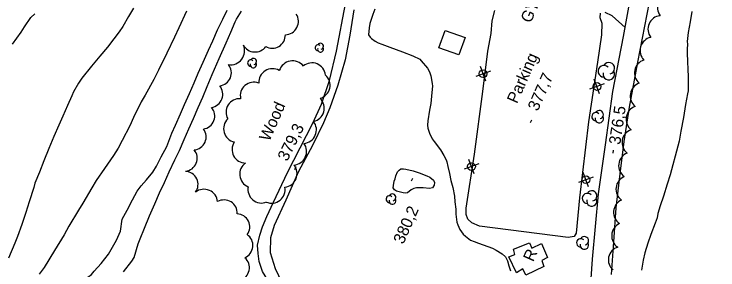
# Model space of a CAD drawing. Extents: x 287698 to 290158, y 5234163 to 5237182.
# Drawn here: x 288774.6 to 288956.3, y 5234855.5 to 5234921.6 of the extents above; entities that cross this region are included whole.
import ezdxf

# ---------------------------------------------------------------- set-up
doc = ezdxf.new("R2010")
doc.units = 0
for name, color, linetype in [('Niveau 1', 7, 'Continuous'), ('Niveau 19', 7, 'Continuous'), ('Niveau 2', 7, 'Continuous'), ('Niveau 21', 7, 'Continuous'), ('Niveau 3', 7, 'Continuous'), ('Niveau 31', 7, 'Continuous'), ('Niveau 36', 7, 'Continuous'), ('Niveau 44', 7, 'Continuous'), ('Niveau 52', 7, 'Continuous')]:
    doc.layers.add(name, color=color, linetype=linetype)

msp = doc.modelspace()

# ---------------------------------------------------------------- linework, layer by layer
at = {"layer": 'Niveau 1'}
for points in [[(288774.17, 5234913.81), (288776.43, 5234916.88), (288777.24, 5234918.29), (288778.95, 5234920.67), (288779.93, 5234921.69)], [(288880.18, 5234876.71), (288878.46, 5234876.71), (288877.8, 5234876.57), (288877.12, 5234876.24), (288876.16, 5234875.43), (288875.57, 5234875.31), (288875.06, 5234875.4), (288873.31, 5234875.84), (288872.77, 5234876.22), (288872.47, 5234876.73), (288872.51, 5234877.3), (288872.71, 5234878.44), (288872.97, 5234879.08), (288873.1, 5234879.85), (288873.53, 5234880.81), (288873.97, 5234881.3), (288874.39, 5234881.62), (288875.08, 5234881.62), (288875.69, 5234881.51), (288877.63, 5234881.11), (288879.11, 5234880.62), (288881.14, 5234879.86), (288881.89, 5234879.46), (288882.87, 5234878.7), (288883.13, 5234878.08), (288883.06, 5234877.38), (288882.57, 5234876.76), (288881.86, 5234876.56), (288880.18, 5234876.71)]]:
    msp.add_lwpolyline(points, dxfattribs=at)
at = {"layer": 'Niveau 19'}
for points in [[(288839.86, 5234869.3), (288841.53, 5234872.99), (288845.2, 5234880.65), (288851.7, 5234893.44), (288853.92, 5234898.35), (288856.04, 5234904.47), (288857.79, 5234911.98), (288860.11, 5234924.2)], [(288862.3, 5234922.68), (288861.25, 5234916.18), (288860.09, 5234909.73), (288858.16, 5234903.22), (288856.12, 5234897.35), (288854.45, 5234893.48), (288851.58, 5234887.67), (288847.97, 5234880.93), (288844.71, 5234873.51), (288841.72, 5234867.03), (288840.74, 5234863.77), (288840.7, 5234859.98), (288841.98, 5234855.92), (288843.73, 5234852.3)], [(288857.44, 5234838.79), (288853.16, 5234839.45), (288850.82, 5234840.45), (288848.62, 5234841.61), (288846.58, 5234843.94), (288841.74, 5234850.38), (288840.13, 5234852.86), (288838.68, 5234855.1), (288837.81, 5234857.67), (288837.57, 5234859.79), (288837.44, 5234861.9), (288838.04, 5234864.52), (288838.71, 5234866.69), (288839.86, 5234869.3)]]:
    msp.add_lwpolyline(points, dxfattribs=at)
at = {"layer": 'Niveau 2'}
for points in [[(288805.44, 5234923.13), (288804.15, 5234921), (288802.66, 5234918.39), (288801.74, 5234916.97), (288800.32, 5234915.22), (288798.69, 5234913.04), (288796.71, 5234910.68), (288794.54, 5234908.12), (288792.11, 5234905.02), (288791.25, 5234903.79), (288789.96, 5234901.48), (288789.53, 5234900.5), (288788.39, 5234897.99), (288787.16, 5234895.2), (288786.15, 5234892.91), (288784.84, 5234889.95), (288783.54, 5234886.85), (288782.25, 5234883.71), (288781.11, 5234880.79), (288779.98, 5234877.93), (288779.65, 5234876.82), (288778.47, 5234873.13)], [(288819.07, 5234922.36), (288817.08, 5234918.06), (288815.98, 5234915.65), (288813.98, 5234911.48), (288811.91, 5234907.12), (288810.64, 5234904.67), (288808.44, 5234900.61), (288807.43, 5234898.89), (288805.43, 5234894.84), (288804.46, 5234892.72), (288802.53, 5234888.93), (288801.46, 5234886.98), (288800.25, 5234885.07), (288797.96, 5234881.68), (288795.79, 5234878.59), (288794.7, 5234876.75), (288792.35, 5234872.79), (288791.21, 5234870.97), (288788.75, 5234866.83), (288787.53, 5234864.62), (288785.02, 5234860.51), (288782.39, 5234856.18), (288781.1, 5234854.39)], [(288802.06, 5234865.55), (288802.53, 5234868.62), (288803.76, 5234870.96), (288805.16, 5234873.58), (288806.4, 5234875.89), (288807.38, 5234877.25), (288808.79, 5234878.82), (288810.37, 5234880.76), (288811.31, 5234882.33), (288812.59, 5234884.72), (288814.06, 5234887.4), (288814.3, 5234888.04), (288815.35, 5234890.85), (288816.24, 5234892.94), (288817.51, 5234895.83), (288818.58, 5234898.25), (288819.83, 5234901.08), (288821.05, 5234903.85), (288822.13, 5234906.32), (288823.41, 5234909.21), (288824.8, 5234912.3), (288825.87, 5234914.72), (288827.13, 5234917.5), (288828.48, 5234920.28), (288829.55, 5234922.64)], [(288832, 5234920.25), (288833.27, 5234922.32)], [(288867.71, 5234922.82), (288867.19, 5234921.49), (288866.41, 5234919.13), (288866.21, 5234918.02), (288866.09, 5234916.26), (288866.47, 5234915.66), (288866.88, 5234915.25), (288867.82, 5234914.59), (288868.6, 5234914.17), (288869.53, 5234913.78), (288871.59, 5234913.05), (288874.87, 5234911.83), (288877.53, 5234910.77), (288879.3, 5234909.91), (288879.66, 5234909.54), (288881.34, 5234907.62), (288881.86, 5234906.65), (288882.16, 5234905.61), (288882.53, 5234903.69), (288882.56, 5234902.94), (288882.46, 5234901.35), (288882.14, 5234898.48), (288881.84, 5234896.79), (288881.35, 5234894.01), (288881.3, 5234892.88), (288881.42, 5234892.17), (288881.85, 5234890.82), (288882.53, 5234889.38), (288883.04, 5234888.72), (288884.67, 5234886.54), (288885.55, 5234885.11), (288886.14, 5234883.97), (288886.28, 5234883.47), (288886.53, 5234882.25), (288887, 5234880.42), (288887.33, 5234878.62), (288887.8, 5234876.77), (288888.28, 5234874.57), (288888.38, 5234873.13), (288888.6, 5234871.2), (288888.62, 5234869.92), (288888.85, 5234867.85), (288889.09, 5234867.18), (288889.63, 5234865.99), (288890.54, 5234864.77), (288891.13, 5234864.22), (288892.41, 5234863.2), (288893.32, 5234862.82), (288894.43, 5234862.44), (288896.88, 5234861.6), (288898.05, 5234861.11), (288899.06, 5234860.59), (288900.59, 5234859.69), (288901.43, 5234858.93), (288901.97, 5234857.86), (288902.27, 5234856.57), (288902.7, 5234855.32)], [(288949.57, 5234922.25), (288949.1, 5234919.61), (288948.61, 5234916.81), (288948.33, 5234914.53), (288948.37, 5234913.83), (288948.29, 5234912.5), (288948.34, 5234911.36), (288948.45, 5234909.49), (288948.46, 5234907.11), (288948.55, 5234905.63), (288948.62, 5234903.31), (288948.56, 5234901.79), (288948.42, 5234900.99), (288947.93, 5234898.25), (288947.34, 5234894.86), (288946.73, 5234891.39), (288946.27, 5234888.79), (288945.95, 5234887.47), (288945.21, 5234884.86), (288944.64, 5234882.7), (288943.9, 5234880.07), (288943.14, 5234877.65), (288942.2, 5234874.59), (288941.35, 5234872.07), (288940.75, 5234870.09), (288940.55, 5234868.93), (288940.05, 5234867.57), (288938.99, 5234864.71), (288938.21, 5234862.45), (288937.44, 5234859.91), (288936.96, 5234858), (288936.5, 5234855.42)], [(288802.81, 5234855.03), (288804.97, 5234857.79), (288805.63, 5234858.77), (288806.63, 5234862.29), (288807.16, 5234863.59), (288808.29, 5234866.3), (288809.58, 5234869.5), (288810.9, 5234872.56), (288812.15, 5234875.4), (288813.38, 5234878.12), (288814.66, 5234880.82), (288816.07, 5234883.99), (288817.27, 5234886.36), (288818.5, 5234889.17), (288819.69, 5234891.95), (288820.89, 5234894.66), (288822.12, 5234897.44), (288823.31, 5234900.15), (288824.41, 5234902.86), (288825.71, 5234905.97), (288827.55, 5234910.14), (288829.32, 5234914.14), (288830.54, 5234916.93), (288831.7, 5234919.56), (288832, 5234920.25)], [(288778.47, 5234873.13), (288777.61, 5234870.33), (288776.59, 5234867.24), (288775.49, 5234864.18), (288774.78, 5234862.41), (288773.16, 5234858.6)], [(288797.03, 5234857.19), (288798.93, 5234859.57), (288801.03, 5234863.19), (288802.06, 5234865.55)], [(288774.12, 5234837.27), (288776.28, 5234839.62), (288777.32, 5234840.61), (288779.52, 5234842.9), (288781.21, 5234844.79), (288782.92, 5234846.9), (288784.86, 5234848.87), (288785.35, 5234849.15), (288787.78, 5234850.75), (288789.89, 5234851.89), (288791.11, 5234852.39), (288793.65, 5234853.66), (288794.56, 5234854.36), (288795.28, 5234855.21), (288797.03, 5234857.19)]]:
    msp.add_lwpolyline(points, dxfattribs=at)
at = {"layer": 'Niveau 21'}
for points in [[(288922.94, 5234844.51), (288923.87, 5234858.3), (288925.42, 5234875.13), (288927.29, 5234887.83), (288929.11, 5234901.59), (288931.93, 5234915.83), (288933.92, 5234927.24), (288936.33, 5234942.64), (288937.38, 5234949.4), (288938.45, 5234954.47), (288939.61, 5234958.71), (288941.21, 5234963.3), (288943.54, 5234967.66), (288946.48, 5234973.06), (288949.16, 5234979.57), (288952.18, 5234987.51), (288955.03, 5234994.58), (288959.1, 5235002.7)], [(288959.42, 5234990.64), (288955.67, 5234983.34), (288953.1, 5234975.97), (288949.25, 5234966.62), (288946.73, 5234960.36), (288945.04, 5234954), (288942.16, 5234941.12), (288939.76, 5234930.98), (288935.54, 5234909.21), (288933.35, 5234897.51), (288931.99, 5234888.65), (288930.97, 5234880.34), (288929.91, 5234871.55), (288929.29, 5234862.75), (288928.74, 5234854.31)]]:
    msp.add_lwpolyline(points, dxfattribs=at)
at = {"layer": 'Niveau 3'}
for p, q in [((288907.9, 5234893.56), (288908.22, 5234894.29)), ((288929.21, 5234885.66), (288929.35, 5234886.44)), ((288847.04, 5234881.48), (288847.4, 5234882.19)), ((288877.17, 5234878.49), (288877.49, 5234879.22))]:
    msp.add_line(p, q, dxfattribs=at)
at = {"layer": 'Niveau 31'}
for points in [[(288889.4, 5234911.03), (288884.25, 5234912.85), (288885.84, 5234917.36), (288890.99, 5234915.54)], [(288911.35, 5234856.38), (288906.65, 5234854.16), (288905.94, 5234855.77), (288904.24, 5234854.79), (288902.29, 5234858.91), (288903.82, 5234859.53), (288903.47, 5234860.86), (288907.65, 5234862.49), (288908.26, 5234861.13), (288910.75, 5234862.31), (288912.3, 5234858.69), (288910.79, 5234857.92)]]:
    msp.add_lwpolyline(points, close=True, dxfattribs=at)
at = {"layer": 'Niveau 36'}
for p, q in [((288897.54, 5234906.86), (288893.79, 5234905.49)), ((288896.35, 5234904.3), (288894.98, 5234908.05)), ((288926.91, 5234903.57), (288923.16, 5234902.2)), ((288925.72, 5234901.01), (288924.35, 5234904.76)), ((288893.34, 5234880.32), (288891.97, 5234884.07)), ((288894.53, 5234882.88), (288890.78, 5234881.51)), ((288922.88, 5234876.94), (288921.51, 5234880.69)), ((288924.07, 5234879.5), (288920.32, 5234878.13))]:
    msp.add_line(p, q, dxfattribs=at)
for centre in [(288895.66, 5234906.18), (288925.03, 5234902.89), (288892.65, 5234882.2), (288922.19, 5234878.82)]:
    msp.add_ellipse(centre, major_axis=(-0.907, 0.42), ratio=0.999982, dxfattribs=at)
at = {"layer": 'Niveau 44'}
for centre, radius, start, end in [((288853.05, 5234912.91), 0.754, 44.1154, 269.804), ((288853.7, 5234912.53), 0.754, 166.9369, 29.6212), ((288853.7, 5234913.29), 0.754, 282.2692, 149.7263), ((288835.67, 5234908.94), 0.811, 44.1154, 269.804), ((288836.36, 5234908.54), 0.811, 166.9369, 29.6212), ((288836.36, 5234909.35), 0.811, 282.2692, 149.7263), ((288846.47, 5234905.88), 3.61, 39.5583, 161.2791), ((288851.48, 5234905.47), 3.51, 6.2069, 129.3802), ((288928.11, 5234907.58), 1.49, 282.2692, 149.7263), ((288827.28, 5234906.43), 3.4, 276.626, 38.4458), ((288841.31, 5234903.91), 3.58, 60.901, 182.4101), ((288926.83, 5234906.83), 1.49, 44.1154, 269.804), ((288928.11, 5234906.08), 1.49, 166.9369, 29.6212), ((288825.07, 5234900.86), 3.4, 278.3012, 40.1357), ((288936.06, 5234894.42), 3.5, 109.1073, 230.9202), ((288822.98, 5234895.27), 3.4, 278.6015, 40.6921), ((288924.74, 5234895.1), 1.06, 44.1154, 269.804), ((288925.65, 5234895.63), 1.06, 282.2692, 149.7263), ((288832.18, 5234891.99), 3.51, 134.1647, 257.5986), ((288925.65, 5234894.57), 1.06, 166.9369, 29.6212), ((288820.78, 5234889.88), 3.39, 275.0891, 36.8088), ((288834.36, 5234886.64), 3.51, 146.5809, 269.8698), ((288934.13, 5234882.46), 3.49, 112.3632, 234.4801), ((288836.34, 5234880.24), 3.51, 124.4895, 247.7811), ((288823.59, 5234872.79), 3.56, 5.8222, 127.8048), ((288838.44, 5234876.3), 3.5, 168.6226, 292.4048), ((288923.71, 5234874.64), 1.33, 282.2692, 149.7263), ((288871.5, 5234873.8), 0.884, 44.1154, 269.804), ((288872.26, 5234874.25), 0.884, 282.2692, 149.7263), ((288922.56, 5234873.98), 1.33, 44.1154, 269.804), ((288872.26, 5234873.36), 0.884, 166.9369, 29.6212), ((288923.71, 5234873.31), 1.33, 166.9369, 29.6212), ((288920.86, 5234862.49), 1.09, 44.1154, 269.804), ((288921.8, 5234863.04), 1.09, 282.2692, 149.7263), ((288921.8, 5234861.94), 1.09, 166.9369, 29.6212), ((288831.92, 5234856.09), 3.41, 287.7706, 49.3451)]:
    msp.add_arc(centre, radius, start, end, dxfattribs=at)
for centre, major_axis, ratio, start_param, end_param in [((288944.18, 5234923.2), (2, -2.86), 0.999984, 2.594488, 4.7227), ((288844.54, 5234919.7), (3.05, -1.61), 0.999802, 5.21778, 7.349791), ((288941.69, 5234917.69), (2.11, -2.79), 0.999984, 2.594948, 4.718167), ((288841.2, 5234916.18), (2.97, 1.67), 0.999984, 3.692074, 5.788816), ((288939.65, 5234912.15), (-3.28, 1.21), 0.999022, 5.278382, 7.406117), ((288830.46, 5234912.13), (2.89, -2.21), 0.99998, 5.220334, 7.34848), ((288836.79, 5234915.2), (3.41, -0.01), 0.999984, 3.636306, 5.660231), ((288938.22, 5234906.4), (-3.43, 0.67), 0.999351, 5.220405, 7.344095), ((288852.65, 5234903.22), (0.8, 3.41), 0.999985, 3.635313, 5.789465), ((288836.49, 5234900.48), (-2.65, -2.3), 0.999985, 3.637338, 5.78744), ((288937.11, 5234900.44), (-3.27, 1.22), 0.999887, 5.404538, 7.533363), ((288832.81, 5234896.22), (-1.89, -2.96), 0.999985, 3.637316, 5.787462), ((288851.15, 5234897.27), (0.96, 3.37), 0.999985, 3.63454, 5.790238), ((288849.13, 5234891.69), (3.15, -1.54), 0.999916, 5.251281, 7.402421), ((288934.99, 5234888.4), (-3.43, 0.61), 0.999995, 5.219885, 7.349576), ((288846.58, 5234886.12), (3.19, -1.48), 0.999915, 5.216723, 7.346105), ((288818.47, 5234884.36), (1.27, 3.14), 0.999984, 3.638589, 5.786189), ((288844.12, 5234880.37), (2.99, -1.85), 0.999772, 5.376843, 7.529209), ((288818.69, 5234877.6), (-1.45, 3.05), 0.999984, 3.634173, 5.790605), ((288933.43, 5234876.39), (-3.47, 0.42), 0.999462, 5.222786, 7.344502), ((288841.07, 5234876.26), (2.74, 2.17), 0.999985, 3.632134, 5.792644), ((288828.81, 5234870.22), (-2.87, 1.78), 0.999984, 3.636175, 5.788602), ((288932.82, 5234870.39), (-3.42, 0.72), 0.999769, 5.34981, 7.472852), ((288832.04, 5234866.63), (-1.47, 3.04), 0.999984, 3.633366, 5.791411), ((288932.33, 5234864.31), (1.52, -3.14), 0.999995, 3.119261, 5.242697), ((288832.79, 5234861.84), (3.42, -0.36), 0.999994, 5.220078, 7.346066), ((288931.49, 5234858.12), (-3.43, 0.69), 0.98774, 5.226471, 7.332003)]:
    msp.add_ellipse(centre, major_axis=major_axis, ratio=ratio, start_param=start_param, end_param=end_param, dxfattribs=at)
at = {"layer": 'Niveau 52'}
for points in [[(288925.9, 5234921.83), (288925.75, 5234920.74), (288926.33, 5234919.2), (288926.23, 5234916.21), (288925.21, 5234909.14), (288922.85, 5234893.8), (288920.5, 5234874.15), (288919.7, 5234865.03), (288919.14, 5234864.15), (288917.65, 5234863.86), (288894.76, 5234866.84), (288892.72, 5234867.71), (288891.73, 5234868.66), (288891.24, 5234869.82), (288891.25, 5234871.48), (288893.46, 5234885.39), (288895.57, 5234901.61), (288896.89, 5234912), (288897.76, 5234916.6), (288898.01, 5234919.86), (288898.66, 5234922.49)], [(288932.33, 5234918.1), (288928.99, 5234921.15), (288927.19, 5234921.99)]]:
    msp.add_lwpolyline(points, dxfattribs=at)

# ---------------------------------------------------------------- texts
at = {"layer": 'Niveau 3'}
for s, rotation, p in [('377,7', 66.1217, (288909.76, 5234896.34)), ('376,5', 81.5364, (288931.04, 5234887.72)), ('379,3', 63.6429, (288845.1, 5234883.38)), ('380,2', 66.1217, (288875.06, 5234861.99))]:
    msp.add_text(s, height=3, rotation=rotation, dxfattribs=at).set_placement(p)
at = {"layer": 'Niveau 31'}
for s, rotation, p in [('GYMNASIUM', 66.1212, (288907.92, 5234919.07)), ('R', 66.1217, (288908.59, 5234857.44))]:
    msp.add_text(s, height=3, rotation=rotation, dxfattribs=at).set_placement(p)
at = {"layer": 'Niveau 44'}
msp.add_text('Wood', height=3, rotation=66.1217, dxfattribs=at).set_placement((288840.46, 5234888.5))
at = {"layer": 'Niveau 52'}
msp.add_text('Parking', height=3, rotation=66.1217, dxfattribs=at).set_placement((288904.41, 5234898.29))

doc.saveas('drawing.dxf')
